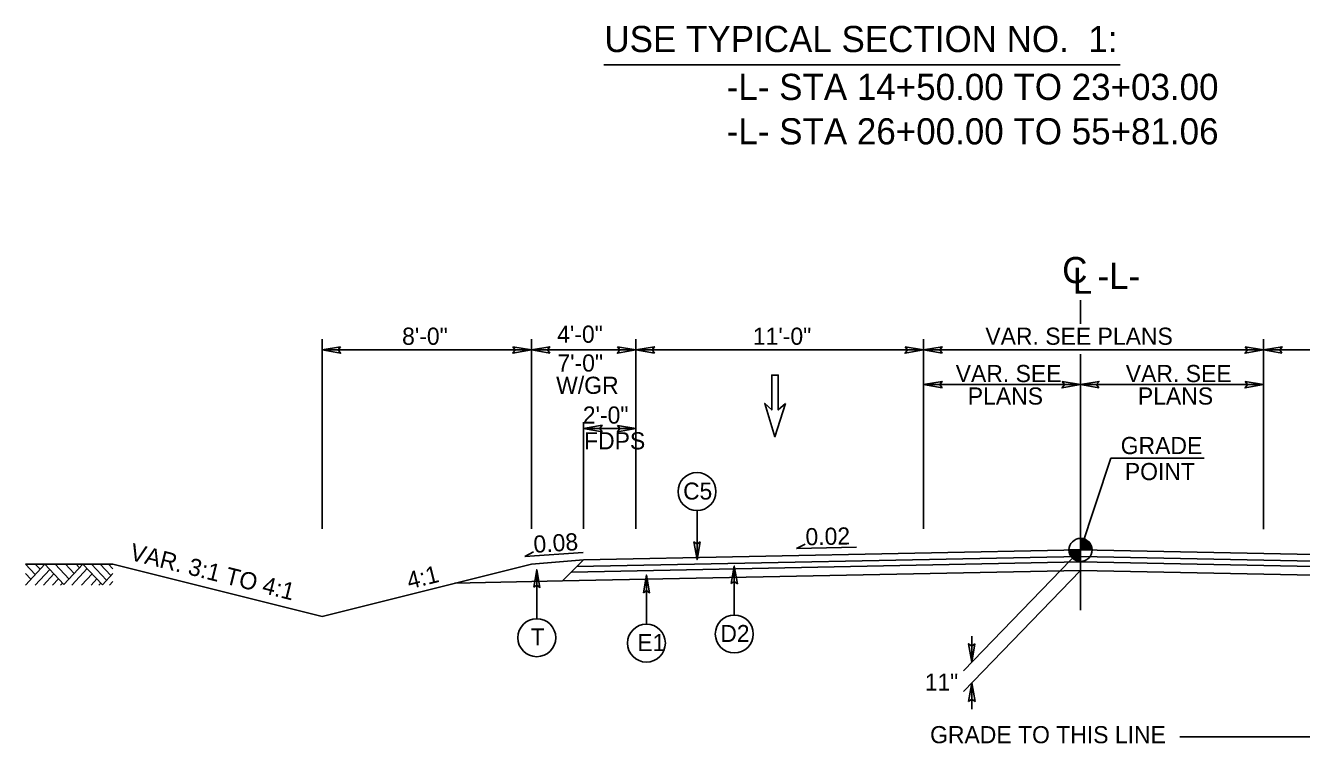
# Model space of a CAD drawing. Extents: x 1901718 to 1902220, y 193828 to 194187.
# Drawn here: x 1902010.35 to 1902059.14, y 193989.75 to 194017.2 of the extents above; entities that cross this region are included whole.
import ezdxf

# ---------------------------------------------------------------- set-up
doc = ezdxf.new("R2010")
doc.units = 0
for name, color, linetype in [('Old_Level_1', 7, 'Continuous'), ('Old_Level_11', 7, 'Continuous'), ('Old_Level_2', 7, 'Continuous'), ('Old_Level_20', 7, 'Continuous'), ('Old_Level_3', 7, 'Continuous'), ('Prop Dimension', 7, 'Continuous'), ('Prop Dimension Text', 7, 'Continuous'), ('Typical Terminator CELL', 7, 'Continuous')]:
    doc.layers.add(name, color=color, linetype=linetype)

# ---------------------------------------------------------------- blocks, each defined once
blk = doc.blocks.new('TERMINATOR')
at = {"layer": 'Typical Terminator CELL'}
blk.add_lwpolyline([(-0.469, 0.081), (0, 0), (-0.471, -0.083), (-0.411, 0)], close=True, dxfattribs=at)

msp = doc.modelspace()

# ---------------------------------------------------------------- linework, layer by layer
at = {"layer": 'Old_Level_1'}
for p, q in [((1902050.692, 194005.797), (1902050.692, 194006.703)), ((1902050.692, 193994.845), (1902050.692, 194004.628)), ((1902050.692, 193997.151), (1902050.692, 193997.592)), ((1902029.445, 193996.901), (1902029.77, 193997.082)), ((1902031.68, 193997.047), (1902029.445, 193996.901)), ((1902050.692, 193997.151), (1902031.692, 193996.771)), ((1902039.825, 193997.206), (1902040.158, 193997.373)), ((1902042.129, 193997.254), (1902039.825, 193997.206)), ((1902050.692, 193997.151), (1902046.216, 193992.526)), ((1902050.251, 193997.151), (1902050.692, 193997.151)), ((1902050.691, 193996.71), (1902050.692, 193997.151)), ((1902050.692, 193997.151), (1902050.691, 193996.71)), ((1902050.692, 193997.151), (1902070.713, 193996.75)), ((1902051.133, 193997.151), (1902050.692, 193997.151)), ((1902010.35, 193996.611), (1902010.725, 193996.208)), ((1902010.35, 193995.806), (1902011.092, 193996.603)), ((1902010.725, 193996.611), (1902010.912, 193996.41)), ((1902011.092, 193996.603), (1902011.816, 193995.824)), ((1902011.483, 193996.611), (1902012.016, 193996.038)), ((1902011.816, 193995.824), (1902012.547, 193996.61)), ((1902011.881, 193996.611), (1902012.214, 193996.252)), ((1902012.283, 193996.611), (1902012.416, 193996.468)), ((1902012.547, 193996.61), (1902013.288, 193995.814)), ((1902012.869, 193996.611), (1902013.449, 193995.988)), ((1902013.202, 193996.611), (1902013.616, 193996.167)), ((1902013.522, 193996.611), (1902013.692, 193996.428)), ((1902013.692, 193996.611), (1902021.692, 193994.611)), ((1902029.692, 193996.611), (1902021.692, 193994.611)), ((1902031.692, 193996.771), (1902029.692, 193996.611)), ((1902031.692, 193996.771), (1902030.885, 193995.963)), ((1902050.692, 193996.692), (1902031.225, 193996.303)), ((1902050.692, 193996.901), (1902031.437, 193996.515)), ((1902050.692, 193996.901), (1902070.968, 193996.495)), ((1902050.692, 193996.692), (1902071.181, 193996.282)), ((1902010.35, 193996.249), (1902010.556, 193996.027)), ((1902010.724, 193995.806), (1902011.278, 193996.402)), ((1902011.033, 193995.806), (1902011.434, 193996.235)), ((1902011.38, 193995.806), (1902011.607, 193996.049)), ((1902012.126, 193995.806), (1902012.712, 193996.434)), ((1902012.496, 193995.806), (1902012.896, 193996.235)), ((1902012.862, 193995.806), (1902013.079, 193996.039)), ((1902013.288, 193995.814), (1902013.692, 193996.249)), ((1902050.692, 193996.359), (1902030.885, 193995.963)), ((1902050.692, 193996.359), (1902046.216, 193991.734)), ((1902050.692, 193996.359), (1902071.521, 193995.942)), ((1902011.691, 193995.806), (1902011.762, 193995.882)), ((1902013.157, 193995.806), (1902013.226, 193995.88)), ((1902013.558, 193995.806), (1902013.692, 193995.949)), ((1902030.885, 193995.963), (1902026.772, 193995.88)), ((1902046.535, 193993.855), (1902046.535, 193992.855)), ((1902046.535, 193992.064), (1902046.535, 193991.064))]:
    msp.add_line(p, q, dxfattribs=at)
for points in [[(1902050.696, 193997.592), (1902050.696, 193997.592), (1902050.696, 193997.151)], [(1902050.705, 193997.592), (1902050.705, 193997.151)], [(1902050.714, 193997.591), (1902050.714, 193997.151)], [(1902050.723, 193997.591), (1902050.723, 193997.151)], [(1902050.732, 193997.59), (1902050.732, 193997.151)], [(1902050.74, 193997.589), (1902050.74, 193997.151)], [(1902050.749, 193997.588), (1902050.749, 193997.151)], [(1902050.758, 193997.587), (1902050.758, 193997.151)], [(1902050.767, 193997.586), (1902050.767, 193997.151)], [(1902050.776, 193997.584), (1902050.776, 193997.151)], [(1902050.785, 193997.582), (1902050.785, 193997.151)], [(1902050.793, 193997.58), (1902050.793, 193997.151)], [(1902050.802, 193997.578), (1902050.802, 193997.151)], [(1902050.811, 193997.575), (1902050.811, 193997.151)], [(1902050.82, 193997.573), (1902050.82, 193997.151)], [(1902050.829, 193997.57), (1902050.829, 193997.151)], [(1902050.837, 193997.567), (1902050.837, 193997.151)], [(1902050.846, 193997.564), (1902050.846, 193997.151)], [(1902050.855, 193997.56), (1902050.855, 193997.151)], [(1902050.864, 193997.556), (1902050.864, 193997.151)], [(1902050.873, 193997.552), (1902050.873, 193997.151)], [(1902050.882, 193997.548), (1902050.882, 193997.151)], [(1902050.89, 193997.545), (1902050.89, 193997.151)], [(1902050.899, 193997.54), (1902050.899, 193997.151)], [(1902050.908, 193997.535), (1902050.908, 193997.151)], [(1902050.917, 193997.53), (1902050.917, 193997.151)], [(1902050.926, 193997.525), (1902050.926, 193997.151)], [(1902050.934, 193997.519), (1902050.934, 193997.151)], [(1902050.943, 193997.513), (1902050.943, 193997.151)], [(1902050.952, 193997.506), (1902050.952, 193997.151)], [(1902050.961, 193997.5), (1902050.961, 193997.151)], [(1902050.97, 193997.494), (1902050.97, 193997.151)], [(1902050.979, 193997.486), (1902050.979, 193997.151)], [(1902050.987, 193997.478), (1902050.987, 193997.151)], [(1902050.996, 193997.47), (1902050.996, 193997.151)], [(1902051.005, 193997.461), (1902051.005, 193997.151)], [(1902050.253, 193997.151), (1902050.253, 193997.103)], [(1902050.262, 193997.151), (1902050.262, 193997.051)], [(1902050.271, 193997.151), (1902050.271, 193997.019)], [(1902050.28, 193997.151), (1902050.28, 193996.993)], [(1902050.289, 193997.151), (1902050.289, 193996.972)], [(1902050.297, 193997.151), (1902050.297, 193996.954)], [(1902050.306, 193997.151), (1902050.306, 193996.937)], [(1902050.315, 193997.151), (1902050.315, 193996.921)], [(1902050.324, 193997.151), (1902050.324, 193996.908)], [(1902050.333, 193997.151), (1902050.333, 193996.895)], [(1902050.342, 193997.151), (1902050.342, 193996.883)], [(1902050.35, 193997.151), (1902050.35, 193996.872)], [(1902050.359, 193997.151), (1902050.359, 193996.862)], [(1902050.368, 193997.151), (1902050.368, 193996.852)], [(1902050.377, 193997.151), (1902050.377, 193996.842)], [(1902050.386, 193997.151), (1902050.386, 193996.833)], [(1902050.395, 193997.151), (1902050.395, 193996.825)], [(1902050.403, 193997.151), (1902050.403, 193996.817)], [(1902050.412, 193997.151), (1902050.412, 193996.81)], [(1902050.421, 193997.151), (1902050.421, 193996.803)], [(1902050.43, 193997.151), (1902050.43, 193996.796)], [(1902050.439, 193997.151), (1902050.439, 193996.79)], [(1902050.447, 193997.151), (1902050.447, 193996.784)], [(1902050.456, 193997.151), (1902050.456, 193996.778)], [(1902050.465, 193997.151), (1902050.465, 193996.772)], [(1902050.474, 193997.151), (1902050.474, 193996.767)], [(1902050.483, 193997.151), (1902050.483, 193996.763)], [(1902050.492, 193997.151), (1902050.492, 193996.758)], [(1902050.5, 193997.151), (1902050.5, 193996.754)], [(1902050.509, 193997.151), (1902050.509, 193996.75)], [(1902050.518, 193997.151), (1902050.518, 193996.746)], [(1902050.527, 193997.151), (1902050.527, 193996.742)], [(1902050.536, 193997.151), (1902050.536, 193996.738)], [(1902050.544, 193997.151), (1902050.544, 193996.735)], [(1902050.553, 193997.151), (1902050.553, 193996.732)], [(1902050.562, 193997.151), (1902050.562, 193996.729)], [(1902050.571, 193997.151), (1902050.571, 193996.727)], [(1902050.58, 193997.151), (1902050.58, 193996.724)], [(1902050.589, 193997.151), (1902050.589, 193996.722)], [(1902050.597, 193997.151), (1902050.597, 193996.72)], [(1902050.606, 193997.151), (1902050.606, 193996.718)], [(1902050.615, 193997.151), (1902050.615, 193996.716)], [(1902050.624, 193997.151), (1902050.624, 193996.715)], [(1902050.633, 193997.151), (1902050.633, 193996.714)], [(1902050.641, 193997.151), (1902050.641, 193996.713)], [(1902050.65, 193997.151), (1902050.65, 193996.712)], [(1902050.659, 193997.151), (1902050.659, 193996.711)], [(1902050.668, 193997.151), (1902050.668, 193996.711)], [(1902050.677, 193997.151), (1902050.677, 193996.71)], [(1902050.686, 193997.151), (1902050.686, 193996.71), (1902050.686, 193996.71)], [(1902051.014, 193997.452), (1902051.014, 193997.151)], [(1902051.023, 193997.443), (1902051.023, 193997.151)], [(1902051.032, 193997.432), (1902051.032, 193997.151)], [(1902051.04, 193997.421), (1902051.04, 193997.151)], [(1902051.049, 193997.409), (1902051.049, 193997.151)], [(1902051.058, 193997.397), (1902051.058, 193997.151)], [(1902051.067, 193997.383), (1902051.067, 193997.151)], [(1902051.076, 193997.368), (1902051.076, 193997.151)], [(1902051.084, 193997.352), (1902051.084, 193997.151)], [(1902051.093, 193997.334), (1902051.093, 193997.151)], [(1902051.102, 193997.313), (1902051.102, 193997.151)], [(1902051.111, 193997.289), (1902051.111, 193997.151)], [(1902051.12, 193997.258), (1902051.12, 193997.151)], [(1902051.129, 193997.213), (1902051.129, 193997.151)], [(1902010.35, 193996.611), (1902013.692, 193996.611)], [(1902061.17, 193996.149), (1902059.885, 193990.006), (1902054.494, 193990.006)]]:
    msp.add_lwpolyline(points, dxfattribs=at)
msp.add_circle((1902050.692, 193997.151), 0.441, dxfattribs=at)
for start, end in [(359.9905, 89.9905), (179.9905, 269.9905)]:
    msp.add_arc((1902050.692, 193997.151), 0.441, start, end, dxfattribs=at)
at = {"layer": 'Old_Level_11'}
for p, q in [((1902032.462, 194015.689), (1902052.205, 194015.689)), ((1902036.027, 193998.657), (1902036.027, 193996.783)), ((1902037.451, 193994.661), (1902037.451, 193996.535)), ((1902029.9, 193994.519), (1902029.9, 193996.393)), ((1902034.092, 193994.312), (1902034.092, 193996.187))]:
    msp.add_line(p, q, dxfattribs=at)
for points in [[(1902036.142, 193997.454), (1902036.027, 193996.783), (1902035.907, 193997.458), (1902036.027, 193997.372)], [(1902037.336, 193995.864), (1902037.451, 193996.535), (1902037.571, 193995.86), (1902037.451, 193995.946)], [(1902029.784, 193995.722), (1902029.9, 193996.393), (1902030.019, 193995.718), (1902029.9, 193995.804)], [(1902033.977, 193995.515), (1902034.092, 193996.187), (1902034.212, 193995.511), (1902034.092, 193995.597)]]:
    msp.add_lwpolyline(points, close=True, dxfattribs=at)
for centre in [(1902036.027, 193999.382), (1902037.452, 193993.936), (1902029.9, 193993.794), (1902034.092, 193993.587)]:
    msp.add_circle(centre, 0.725, dxfattribs=at)
at = {"layer": 'Old_Level_3'}
for q in [(1902050.692, 193997.151), (1902055.419, 194000.655)]:
    msp.add_line((1902051.855, 194000.655), q, dxfattribs=at)
at = {"layer": 'Prop Dimension'}
for p, q in [((1902021.692, 193997.962), (1902021.692, 194005.214)), ((1902029.692, 193997.962), (1902029.692, 194005.214)), ((1902033.692, 193997.962), (1902033.692, 194005.214)), ((1902033.692, 194004.795), (1902044.692, 194004.795)), ((1902044.692, 193997.962), (1902044.692, 194005.214)), ((1902044.692, 194004.795), (1902057.692, 194004.795)), ((1902057.692, 193997.942), (1902057.692, 194005.214)), ((1902057.692, 194004.795), (1902068.692, 194004.795)), ((1902044.692, 194003.471), (1902050.692, 194003.471)), ((1902050.692, 194003.471), (1902057.692, 194003.471)), ((1902031.692, 193997.962), (1902031.692, 194002.041)), ((1902031.692, 194001.791), (1902033.692, 194001.791))]:
    msp.add_line(p, q, dxfattribs=at)
msp.add_lwpolyline([(1902039.405, 194002.75), (1902039.134, 194002.5), (1902039.134, 194003.834), (1902038.884, 194003.834), (1902038.884, 194002.5), (1902038.614, 194002.75), (1902039.009, 194001.479)], close=True, dxfattribs=at)
msp.add_lwpolyline([(1902039.405, 194002.75), (1902039.134, 194002.5), (1902039.134, 194003.834), (1902038.884, 194003.834), (1902038.884, 194002.5), (1902038.614, 194002.75), (1902039.009, 194001.479)], close=True, dxfattribs=at)
at = {"layer": 'Prop Dimension Text'}
for p, q in [((1902021.692, 194004.795), (1902029.692, 194004.795)), ((1902029.692, 194004.795), (1902033.692, 194004.795))]:
    msp.add_line(p, q, dxfattribs=at)

# ---------------------------------------------------------------- block references
at = {"layer": 'Old_Level_1', "xscale": 1.5, "yscale": 1.5}
for p, rotation in [((1902046.535, 193992.855), -90), ((1902046.535, 193992.064), 90)]:
    msp.add_blockref('TERMINATOR', p, dxfattribs=dict(at, rotation=rotation))
at = {"layer": 'Prop Dimension', "xscale": 1.5, "rotation": 180}
for p, yscale in [((1902021.692, 194004.795), -1.5), ((1902029.692, 194004.795), 1.5), ((1902033.692, 194004.795), 1.5), ((1902044.692, 194004.795), 1.5), ((1902057.692, 194004.795), 1.5), ((1902044.692, 194003.471), 1.5), ((1902050.692, 194003.471), 1.5), ((1902031.692, 194001.791), 1.5)]:
    msp.add_blockref('TERMINATOR', p, dxfattribs=dict(at, yscale=yscale))
at = {"layer": 'Prop Dimension', "xscale": 1.5, "yscale": 1.5}
for p in [(1902029.692, 194004.795), (1902033.692, 194004.795), (1902044.692, 194004.795), (1902057.692, 194004.795), (1902050.692, 194003.471), (1902057.692, 194003.471), (1902033.692, 194001.791)]:
    msp.add_blockref('TERMINATOR', p, dxfattribs=at)

# ---------------------------------------------------------------- texts
at = {"layer": 'Old_Level_1'}
for s, rotation, p in [('VAR. 3:1 TO 4:1', 345.9638, (1902014.301, 193996.778)), ('4:1', 14.0362, (1902025.025, 193995.641))]:
    msp.add_text(s, height=0.656, rotation=rotation, dxfattribs=at).set_placement(p)
for s, height, p in [('11"', 0.6491, (1902044.74, 193991.772)), ('GRADE TO THIS LINE', 0.656, (1902044.939, 193989.76))]:
    msp.add_text(s, height=height, dxfattribs=at).set_placement(p)
at = {"layer": 'Old_Level_11'}
for s, p in [('USE TYPICAL SECTION NO.  1:', (1902032.486, 194016.183)), ('-L- STA 14+50.00 TO 23+03.00', (1902037.162, 194014.352)), ('-L- STA 26+00.00 TO 55+81.06', (1902037.162, 194012.654))]:
    msp.add_text(s, height=1, dxfattribs=at).set_placement(p)
at = {"layer": 'Old_Level_2'}
msp.add_text('C', height=1, dxfattribs=at).set_placement((1902049.991, 194007.349))
for s, height, rotation, p in [('L', 1, 359.9469, (1902050.393, 194006.945)), ('-L-', 1, 359.9469, (1902051.341, 194007.128)), ('0.02', 0.656, 1.1916, (1902040.181, 193997.325)), ('0.08', 0.656, 3.7166, (1902029.795, 193997.035))]:
    msp.add_text(s, height=height, rotation=rotation, dxfattribs=at).set_placement(p)
at = {"layer": 'Old_Level_20'}
for s, height, p in [('C5', 0.6491, (1902035.498, 193999.076)), ('T', 0.649, (1902029.672, 193993.501)), ('D2', 0.6491, (1902036.925, 193993.632)), ('E1', 0.6491, (1902033.747, 193993.284))]:
    msp.add_text(s, height=height, dxfattribs=at).set_placement(p)
at = {"layer": 'Old_Level_3'}
for s, p in [('GRADE', (1902052.228, 194000.813)), ('POINT', (1902052.386, 193999.819))]:
    msp.add_text(s, height=0.656, dxfattribs=at).set_placement(p)
at = {"layer": 'Prop Dimension'}
for s, p in [('11\'-0" ', (1902038.162, 194004.993)), ('VAR. SEE PLANS', (1902047.053, 194004.993)), ('VAR. SEE', (1902045.919, 194003.566)), ('VAR. SEE', (1902052.422, 194003.566)), ('PLANS', (1902046.381, 194002.706)), ('PLANS', (1902052.885, 194002.706))]:
    msp.add_text(s, height=0.656, dxfattribs=at).set_placement(p)
for s, p in [('2\'-0"', (1902031.66, 194001.979)), ('FDPS', (1902031.708, 194000.995))]:
    msp.add_text(s, height=0.656, rotation=360, dxfattribs=at).set_placement(p)
at = {"layer": 'Prop Dimension Text'}
for s, p in [('8\'-0"', (1902024.75, 194004.993)), ('4\'-0"', (1902030.679, 194005.07)), ('7\'-0"', (1902030.688, 194003.969)), ('W/GR', (1902030.641, 194003.116))]:
    msp.add_text(s, height=0.656, dxfattribs=at).set_placement(p)

doc.saveas('drawing.dxf')
